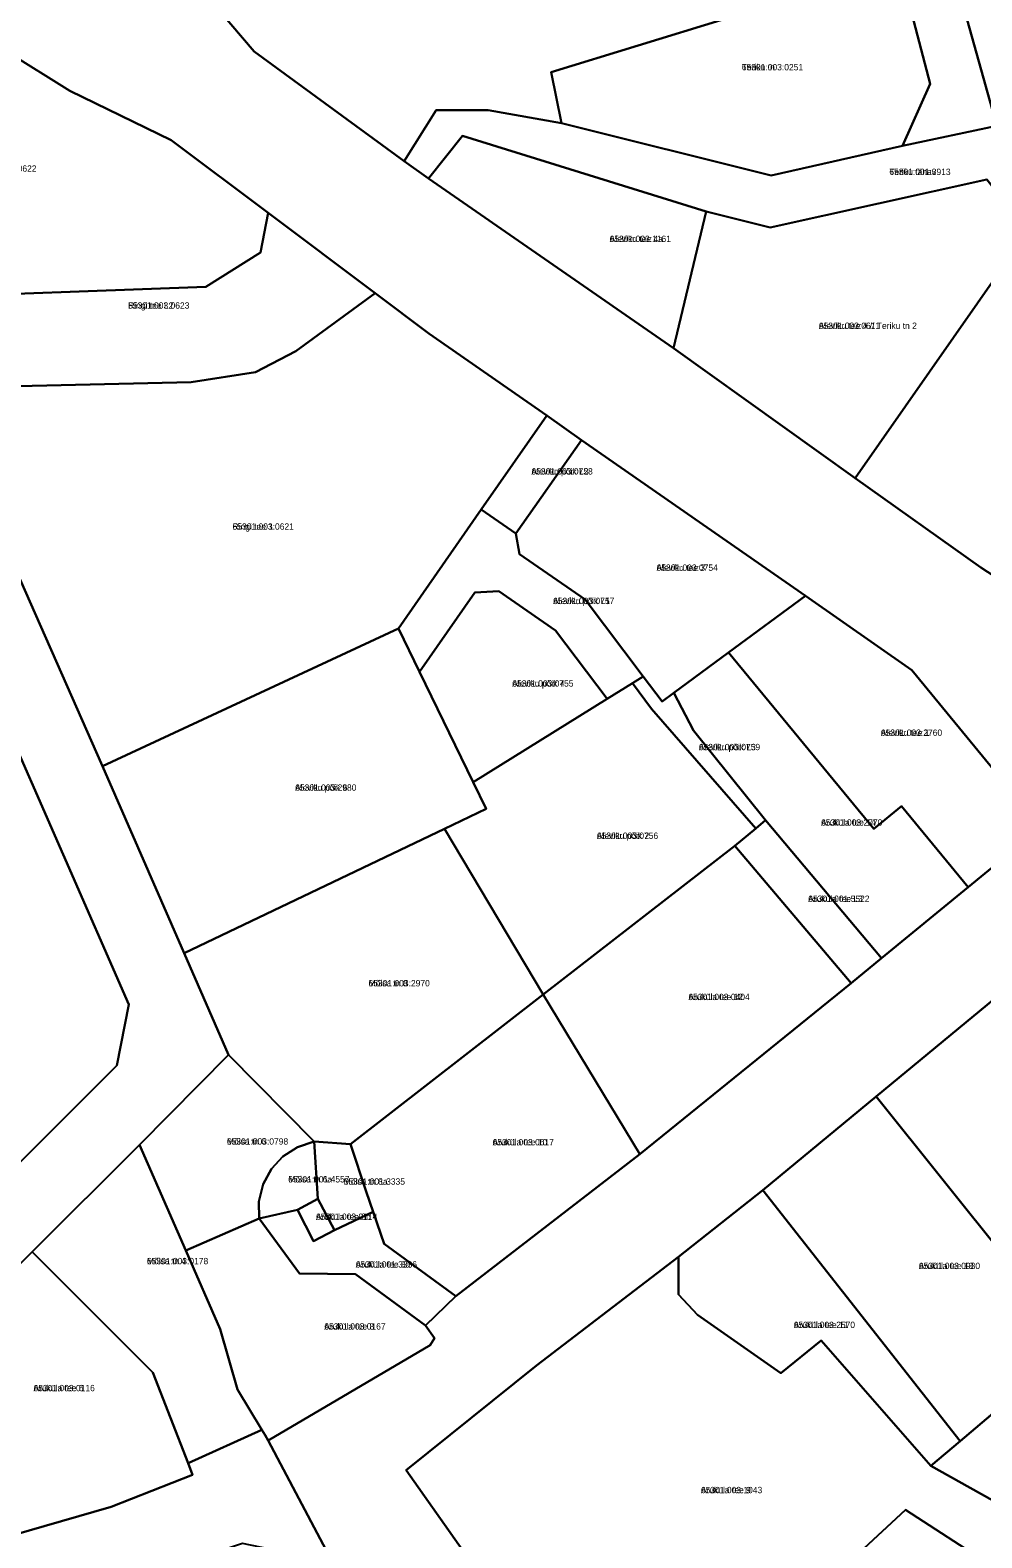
# Model space of a CAD drawing. Extents: x 543236 to 563717, y 6566033 to 6588992.
# Drawn here: x 550737.5 to 550962.8, y 6579920 to 6580276.9 of the extents above; entities that cross this region are included whole.
import ezdxf

# ---------------------------------------------------------------- set-up
doc = ezdxf.new("R2010")
doc.units = 0
for name, color, linetype in [('L_AADRESS', 7, 'Continuous'), ('PIIR', 7, 'Continuous'), ('TUNNUS', 7, 'Continuous')]:
    doc.layers.add(name, color=color, linetype=linetype)

msp = doc.modelspace()

# ---------------------------------------------------------------- linework, layer by layer
at = {"layer": 'PIIR'}
for points in [[(550943.99, 6580249.52), (550950.53, 6580264.18), (550943.16, 6580292.29), (550912.15, 6580392.53), (550921.84, 6580397.2), (550923.15, 6580397.8), (550955.58, 6580292.71), (550966.27, 6580254.24)], [(550764.37, 6580302.62), (550774.2, 6580326.85), (550810.01, 6580343.89), (550858.44, 6580367), (550912.15, 6580392.53), (550943.16, 6580292.29), (550860.83, 6580266.97), (550863.3, 6580254.93), (550845.94, 6580257.95), (550833.66, 6580258), (550826.03, 6580245.87), (550790.58, 6580271.87)], [(550988.47, 6580302.22), (550994.85, 6580280.53), (551028.98, 6580290.31), (551037.91, 6580259.34), (550970.22, 6580240.05), (550966.27, 6580254.24), (550955.58, 6580292.71)], [(550860.83, 6580266.97), (550943.16, 6580292.29), (550950.53, 6580264.18), (550943.99, 6580249.52), (550912.87, 6580242.52), (550863.3, 6580254.93)], [(550656.11, 6580233.31), (550694.23, 6580265.09), (550711.19, 6580273.31), (550732.02, 6580271.89), (550746.93, 6580262.58), (550770.89, 6580250.91), (550793.89, 6580233.64), (550792.06, 6580224.29), (550779.1, 6580216.19), (550706.2, 6580213.48), (550666.9, 6580220.35)], [(550826.03, 6580245.87), (550833.66, 6580258), (550845.94, 6580257.95), (550863.3, 6580254.93), (550912.87, 6580242.52), (550943.99, 6580249.52), (550966.27, 6580254.24), (550970.22, 6580240.05), (551016.76, 6580181.34), (551050.92, 6580182.92), (551053.2, 6580187.63), (551055.71, 6580175.88), (551042.12, 6580175.25), (551017.38, 6580174.1), (551001.75, 6580193.85), (550973.67, 6580229.32), (550963.98, 6580241.56), (550912.7, 6580230.19), (550897.52, 6580234), (550839.87, 6580251.89), (550831.84, 6580241.83)], [(550831.84, 6580241.83), (550839.87, 6580251.89), (550897.52, 6580234), (550889.8, 6580201.63)], [(550897.52, 6580234), (550912.7, 6580230.19), (550963.98, 6580241.56), (550973.67, 6580229.32), (550932.76, 6580170.82), (550889.8, 6580201.63)], [(550706.2, 6580213.48), (550779.1, 6580216.19), (550792.06, 6580224.29), (550793.89, 6580233.64), (550819.17, 6580214.65), (550800.44, 6580200.9), (550790.86, 6580195.92), (550775.62, 6580193.58), (550724.32, 6580192.41), (550717.21, 6580188.33)], [(550973.67, 6580229.32), (551001.75, 6580193.85), (550981.77, 6580165.28), (551001.54, 6580151.45), (551017.38, 6580174.1), (551042.12, 6580175.25), (551038.7, 6580157.14), (551047.58, 6580146.25), (551022.35, 6580126.59), (551009.41, 6580123.79), (550997.63, 6580126.9), (550962.51, 6580149.69), (550932.76, 6580170.82)], [(550717.21, 6580188.33), (550724.32, 6580192.41), (550775.62, 6580193.58), (550790.86, 6580195.92), (550800.44, 6580200.9), (550819.17, 6580214.65), (550831.9, 6580205.09), (550859.83, 6580185.66), (550844.31, 6580163.47), (550824.71, 6580135.28), (550754.63, 6580102.64), (550730.3, 6580157.77), (550725.92, 6580168.4), (550720.54, 6580180.81)], [(550859.83, 6580185.66), (550868.04, 6580179.87), (550852.49, 6580157.77), (550844.31, 6580163.47)], [(550868.04, 6580179.87), (550921.01, 6580142.97), (550902.82, 6580129.58), (550889.89, 6580120.07), (550887.1, 6580117.96), (550882.61, 6580123.9), (550868.85, 6580142.12), (550853.38, 6580152.89), (550852.49, 6580157.77)], [(550712.7, 6579921.9), (550656.64, 6579930.18), (550665.87, 6579939.62), (550681.89, 6579963.11), (550701.76, 6579975.02), (550710.4, 6579984.19), (550758.08, 6580031.83), (550760.86, 6580046.25), (550729.75, 6580117.28), (550710.4, 6580161.62), (550710.58, 6580161.71), (550725.92, 6580168.4), (550730.3, 6580157.77), (550754.63, 6580102.64), (550773.99, 6580058.42), (550784.49, 6580034.32), (550763.41, 6580013.06), (550738, 6579987.69), (550700.7, 6579950.4)], [(550844.31, 6580163.47), (550852.49, 6580157.77), (550853.38, 6580152.89), (550868.85, 6580142.12), (550882.61, 6580123.9), (550880.05, 6580122.31), (550874.08, 6580118.6), (550861.83, 6580134.82), (550848.44, 6580144.14), (550842.81, 6580143.82), (550829.7, 6580124.99), (550824.71, 6580135.28)], [(550829.7, 6580124.99), (550842.81, 6580143.82), (550848.44, 6580144.14), (550861.83, 6580134.82), (550874.08, 6580118.6), (550842.35, 6580098.88)], [(550921.01, 6580142.97), (550946.21, 6580125.37), (550974.9, 6580090.47), (550974.4, 6580086.27), (550959.52, 6580074.03), (550943.75, 6580093.23), (550937.18, 6580087.81), (550902.82, 6580129.58)], [(550754.63, 6580102.64), (550824.71, 6580135.28), (550829.7, 6580124.99), (550842.35, 6580098.88), (550845.42, 6580092.55), (550835.62, 6580087.86), (550773.99, 6580058.42)], [(550894.51, 6580111.08), (550889.89, 6580120.07), (550902.82, 6580129.58), (550937.18, 6580087.81), (550943.75, 6580093.23), (550959.52, 6580074.03), (550939.03, 6580057.18), (550911.53, 6580089.87)], [(550835.62, 6580087.86), (550845.42, 6580092.55), (550842.35, 6580098.88), (550874.08, 6580118.6), (550880.05, 6580122.31), (550884.62, 6580116.26), (550909.24, 6580087.94), (550904.31, 6580083.8), (550858.96, 6580048.6)], [(550880.05, 6580122.31), (550882.61, 6580123.9), (550887.1, 6580117.96), (550889.89, 6580120.07), (550894.51, 6580111.08), (550911.53, 6580089.87), (550909.24, 6580087.94), (550884.62, 6580116.26)], [(550661.3, 6580054.05), (550641.52, 6580059.75), (550666.76, 6580071.14), (550687.92, 6580098.85), (550729.75, 6580117.28), (550760.86, 6580046.25), (550758.08, 6580031.83), (550710.38, 6579984.19), (550672.52, 6580059.7)], [(550939.03, 6580057.18), (550931.8, 6580051.27), (550904.31, 6580083.8), (550909.24, 6580087.94), (550911.53, 6580089.87)], [(550835.62, 6580087.86), (550858.96, 6580048.6), (550813.36, 6580013.19), (550804.79, 6580013.78), (550784.49, 6580034.32), (550773.99, 6580058.42)], [(550904.31, 6580083.8), (550931.8, 6580051.27), (550881.8, 6580010.78), (550858.96, 6580048.6)], [(550858.96, 6580048.6), (550881.8, 6580010.78), (550838.27, 6579977.17), (550821.31, 6579989.55), (550817.09, 6580001.95), (550813.36, 6580013.19)], [(550967.61, 6580049.2), (551017.74, 6579993.54), (550984.71, 6579965.8), (550937.77, 6580024.46)], [(550784.49, 6580034.32), (550804.79, 6580013.78), (550800.81, 6580012.5), (550797.37, 6580010.28), (550794.62, 6580007.31), (550792.65, 6580003.7), (550791.66, 6579999.63), (550791.7, 6579995.59), (550774.4, 6579987.99), (550763.41, 6580013.06)], [(550937.77, 6580024.46), (550984.71, 6579965.8), (550957.62, 6579942.87), (550910.96, 6580002.29)], [(550797.37, 6580010.28), (550800.81, 6580012.5), (550804.79, 6580013.78), (550805.59, 6580000.25), (550800.79, 6579997.65), (550791.7, 6579995.59), (550791.66, 6579999.63), (550792.65, 6580003.7), (550794.62, 6580007.31)], [(550805.59, 6580000.25), (550804.79, 6580013.78), (550813.36, 6580013.19), (550817.09, 6580001.95), (550818.7, 6579997.2), (550809.59, 6579992.86)], [(550738, 6579987.69), (550763.41, 6580013.06), (550774.4, 6579987.99), (550782.5, 6579969.39), (550786.6, 6579955.09), (550792.37, 6579945.57), (550774.9, 6579937.69), (550766.6, 6579959.09)], [(550805.59, 6580000.25), (550809.59, 6579992.86), (550804.63, 6579990.18), (550800.79, 6579997.65)], [(550890.99, 6579977.58), (550891, 6579986.48), (550910.96, 6580002.29), (550957.62, 6579942.87), (550950.65, 6579937), (550924.72, 6579966.72), (550915.23, 6579958.93), (550895.48, 6579972.74)], [(550801.27, 6579982.56), (550791.7, 6579995.59), (550800.79, 6579997.65), (550804.63, 6579990.18), (550809.59, 6579992.86), (550818.7, 6579997.2), (550821.31, 6579989.55), (550838.27, 6579977.17), (550831.1, 6579970.29), (550814.5, 6579982.38)], [(550774.4, 6579987.99), (550791.7, 6579995.59), (550801.27, 6579982.56), (550814.5, 6579982.38), (550831.1, 6579970.29), (550833.2, 6579967.28), (550832.2, 6579965.58), (550793.9, 6579942.99), (550793.15, 6579944.29), (550792.37, 6579945.57), (550786.6, 6579955.09), (550782.5, 6579969.39)], [(550766.6, 6579959.09), (550774.9, 6579937.69), (550775.98, 6579934.9), (550756.7, 6579927.29), (550733.23, 6579920.56), (550731.8, 6579923.9), (550712.7, 6579921.9), (550700.7, 6579950.4), (550738, 6579987.69)], [(550826.55, 6579936), (550857.34, 6579960.82), (550891, 6579986.48), (550890.99, 6579977.58), (550895.48, 6579972.74), (550915.23, 6579958.93), (550924.72, 6579966.72), (550950.65, 6579937), (550971.99, 6579925.08), (550964.69, 6579913.68), (550944.69, 6579926.58), (550933.69, 6579916.4), (550951.68, 6579890.26), (550927.75, 6579910.64), (550906.83, 6579888.46), (550903.2, 6579892.67), (550877.66, 6579874.62), (550862.38, 6579885.09)], [(550573.31, 6579945.77), (550582.71, 6579971.22), (550656.64, 6579930.18), (550712.7, 6579921.9), (550731.8, 6579923.9), (550733.23, 6579920.56), (550756.7, 6579927.29), (550775.98, 6579934.9), (550774.9, 6579937.69), (550792.37, 6579945.57), (550793.15, 6579944.29), (550793.9, 6579942.99), (550809.1, 6579914.26), (550787.82, 6579918.61), (550759.63, 6579909.37), (550733.2, 6579878.12), (550728.82, 6579878.6), (550703.31, 6579881.5), (550696.9, 6579896.5), (550632.78, 6579912.46)], [(550950.65, 6579937), (550957.62, 6579942.87), (550984.71, 6579965.8), (551008.95, 6579934.25), (550975.94, 6579906.43), (550964.69, 6579913.68), (550971.99, 6579925.08)]]:
    msp.add_lwpolyline(points, close=True, dxfattribs=at)
for points in [[(550711.19, 6580273.31), (550745.96, 6580322.05), (550752.52, 6580316.45), (550764.37, 6580302.62), (550790.58, 6580271.87), (550826.03, 6580245.87), (550831.84, 6580241.83), (550889.8, 6580201.63), (550932.76, 6580170.82), (550962.51, 6580149.69), (550997.63, 6580126.9), (551009.41, 6580123.79), (551022.35, 6580126.59), (551047.58, 6580146.25), (551059.82, 6580156.6), (551071.95, 6580165.96), (551093.88, 6580182.3), (551107.91, 6580192.74), (551108.85, 6580193.36), (551140.35, 6580211.64), (551156.54, 6580218.23), (551179.83, 6580227.7), (551194.02, 6580232.16)], [(551220.66, 6580214.61), (551169.46, 6580200.63), (551144.3, 6580186.03), (551120.4, 6580169.1), (551113.87, 6580164.49), (551103.37, 6580157.06), (551090.17, 6580149.68), (551086.53, 6580148.68), (551044.52, 6580114.2), (551019.52, 6580091.69), (550997.06, 6580072.97), (550974.4, 6580086.27), (550974.9, 6580090.47), (550946.21, 6580125.37), (550921.01, 6580142.97), (550868.04, 6580179.87), (550859.83, 6580185.66), (550831.9, 6580205.09), (550819.17, 6580214.65), (550793.89, 6580233.64), (550770.89, 6580250.91), (550746.93, 6580262.58), (550732.02, 6580271.89)], [(550809.1, 6579914.26), (550793.9, 6579942.99), (550832.2, 6579965.58), (550833.2, 6579967.28), (550831.1, 6579970.29), (550838.27, 6579977.17), (550881.8, 6580010.78), (550931.8, 6580051.27), (550939.03, 6580057.18), (550959.52, 6580074.03), (550974.4, 6580086.27), (550997.06, 6580072.97), (550967.61, 6580049.2), (550937.77, 6580024.46), (550910.96, 6580002.29), (550891, 6579986.48), (550857.34, 6579960.82), (550826.55, 6579936), (550862.38, 6579885.09)], [(550933.69, 6579916.4), (550944.69, 6579926.58), (550964.69, 6579913.68)]]:
    msp.add_lwpolyline(points, dxfattribs=at)

# ---------------------------------------------------------------- texts
at = {"layer": 'L_AADRESS'}
for s, p in [('Teriku tn 3', (550905.96, 6580267.4)), ('Teriku tänav', (550940.87, 6580242.63)), ('Aleviku tee 4a', (550874.68, 6580226.76)), ('Ringi tee L2', (550760.73, 6580210.99)), ('Aleviku tee 4 // Teriku tn 2', (550924.19, 6580206.19)), ('Aleviku põik L2', (550856.18, 6580171.72)), ('Ringi tee 1', (550785.45, 6580158.65)), ('Aleviku tee 3', (550885.78, 6580148.92)), ('Aleviku põik L1', (550861.29, 6580141.04)), ('Aleviku põik 4', (550851.63, 6580121.51)), ('Aleviku tee 1', (550938.86, 6580109.85)), ('Aleviku põik L3', (550895.79, 6580106.45)), ('Aleviku põik 6', (550800.25, 6580096.85)), ('Aruküla tee 14', (550924.71, 6580088.59)), ('Aleviku põik 2', (550871.67, 6580085.46)), ('Aruküla tee L3', (550921.67, 6580070.54)), ('Mõisa tn 8', (550817.62, 6580050.53)), ('Aruküla tee 12', (550893.32, 6580047.29)), ('Mõisa tn 6', (550784.1, 6580013.09)), ('Aruküla tee 10', (550846.99, 6580012.89)), ('Mõisa tn 6a', (550798.62, 6580004.12)), ('Mõisa tn 8a', (550811.75, 6580003.59)), ('Aruküla tee 8b', (550805.19, 6579995.26)), ('Mõisa tn 4', (550765.18, 6579984.76)), ('Aruküla tee 8a', (550814.59, 6579983.97)), ('Aruküla tee 13', (550947.84, 6579983.61)), ('Aruküla tee 8', (550807.16, 6579969.29)), ('Aruküla tee 11', (550918.25, 6579969.65)), ('Aruküla tee 6', (550738.34, 6579954.69)), ('Aruküla tee 9', (550896.29, 6579930.55))]:
    msp.add_text(s, height=1.5, dxfattribs=at).set_placement(p)
at = {"layer": 'TUNNUS'}
for s, p in [('65301:003:0251', (550905.96, 6580267.4)), ('65301:003:0622', (550724.55, 6580243.4)), ('65301:001:3913', (550940.87, 6580242.63)), ('65301:003:1161', (550874.68, 6580226.76)), ('65301:003:0623', (550760.73, 6580210.99)), ('65301:003:0611', (550924.19, 6580206.19)), ('65301:003:0758', (550856.18, 6580171.72)), ('65301:003:0621', (550785.45, 6580158.65)), ('65301:003:0754', (550885.78, 6580148.92)), ('65301:003:0757', (550861.29, 6580141.04)), ('65301:003:0755', (550851.63, 6580121.51)), ('65301:003:2760', (550938.86, 6580109.85)), ('65301:003:0759', (550895.79, 6580106.45)), ('65301:003:2980', (550800.25, 6580096.85)), ('65301:003:2770', (550924.71, 6580088.59)), ('65301:003:0756', (550871.67, 6580085.46)), ('65301:001:5522', (550921.67, 6580070.54)), ('65301:003:2970', (550817.62, 6580050.53)), ('65301:003:0404', (550893.32, 6580047.29)), ('65301:003:0798', (550784.1, 6580013.09)), ('65301:003:0617', (550846.99, 6580012.89)), ('65301:001:4557', (550798.62, 6580004.12)), ('65301:001:3335', (550811.75, 6580003.59)), ('65301:003:0114', (550805.19, 6579995.26)), ('65301:003:0178', (550765.18, 6579984.76)), ('65301:001:3336', (550814.59, 6579983.97)), ('65301:003:0930', (550947.84, 6579983.61)), ('65301:003:2570', (550918.25, 6579969.65)), ('65301:003:0167', (550807.16, 6579969.29)), ('65301:003:0116', (550738.34, 6579954.69)), ('65301:003:1043', (550896.29, 6579930.55))]:
    msp.add_text(s, height=1.5, dxfattribs=at).set_placement(p)

doc.saveas('drawing.dxf')
